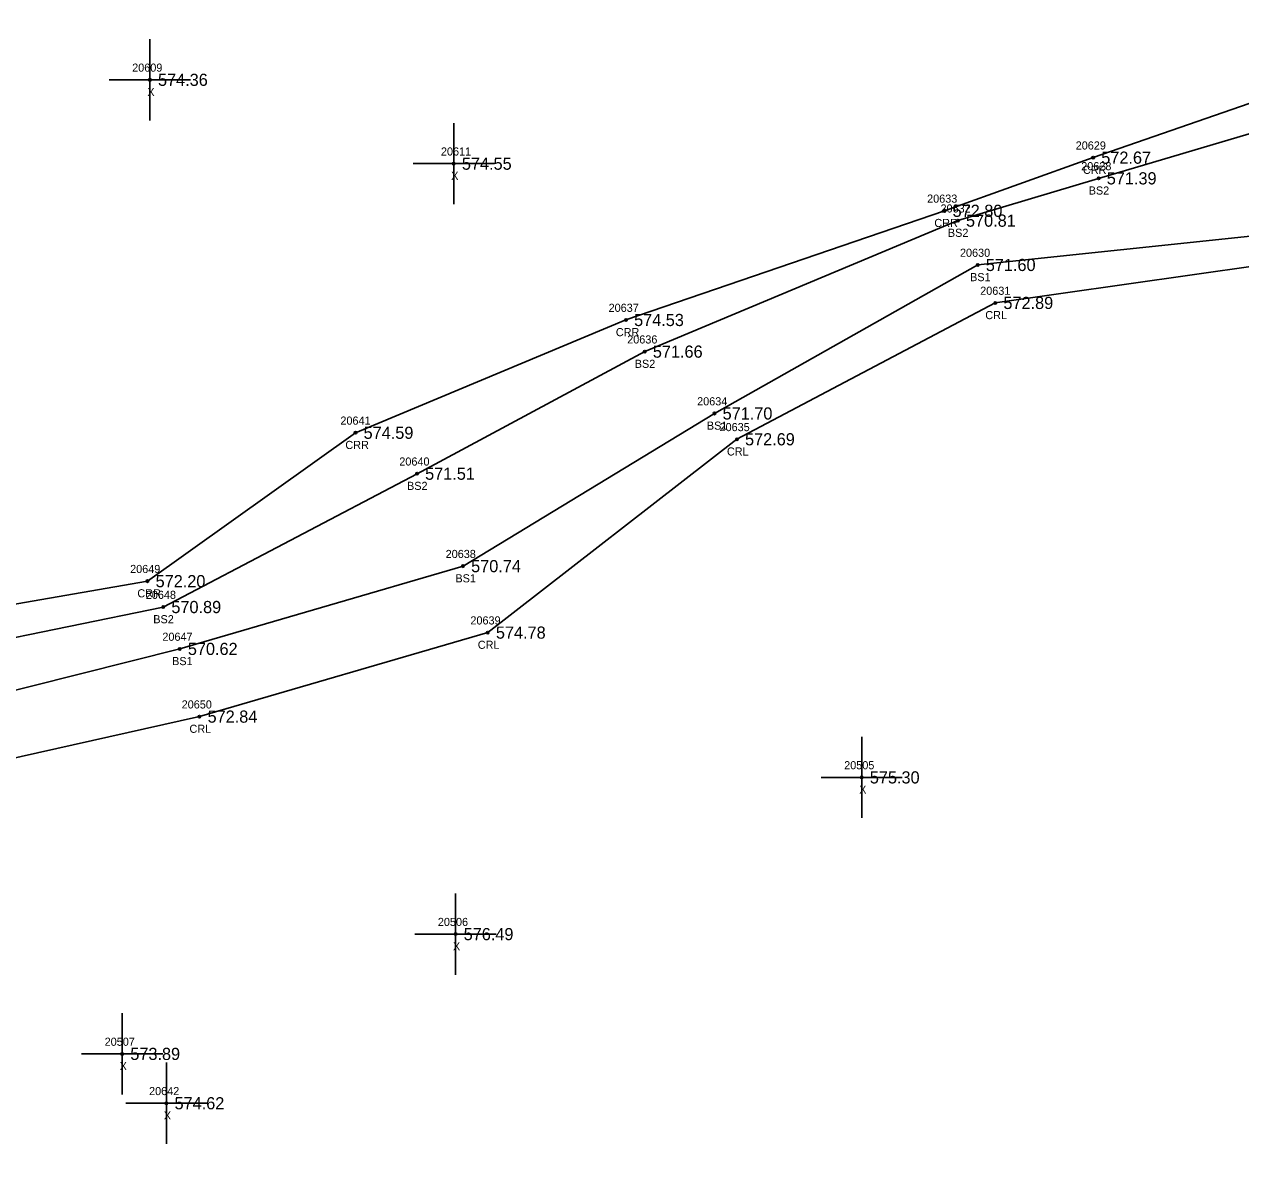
# Model space of a CAD drawing. Extents: x 1664837 to 1666270, y 987403 to 988245.
# Drawn here: x 1665313 to 1665462.9, y 987586.1 to 987728.5 of the extents above; entities that cross this region are included whole.
import ezdxf

# ---------------------------------------------------------------- set-up
doc = ezdxf.new("R2010")
doc.units = 0
for name, color, linetype in [('RD_DTM_BkLn2', 7, 'Continuous'), ('RD_DTM_BkLn_txCode', 7, 'Continuous'), ('RD_EX_H2O', 7, 'Continuous'), ('RD_EX_H2O_txCode', 7, 'Continuous'), ('RD_EX_Misc', 7, 'Continuous'), ('RD_EX_Misc_txCode', 7, 'Continuous'), ('RD_EX_TX_H2O_ELEV', 7, 'Continuous'), ('RD_EX_TX_Misc_ELEV', 7, 'Continuous'), ('RD_SMD_Locator', 7, 'Continuous')]:
    doc.layers.add(name, color=color, linetype=linetype)

msp = doc.modelspace()

# ---------------------------------------------------------------- linework, layer by layer
at = {"layer": 'RD_DTM_BkLn2'}
for points in [[(1665511.23, 987778.14), (1665500.12, 987754.08), (1665496.26, 987735.63), (1665475.45, 987718.43), (1665445.39, 987709.52), (1665428.04, 987704.31), (1665389.45, 987688.17), (1665361.39, 987673.13), (1665330.12, 987656.7), (1665283.57, 987647.17), (1665235.53, 987667.53), (1665208.93, 987663.65), (1665168.4, 987630.38), (1665122.54, 987622.98), (1665093.74, 987624.1), (1665049.09, 987603.27)], [(1665468.58, 987700.71), (1665465.66, 987702.55), (1665430.48, 987698.85), (1665398.05, 987680.55), (1665367.06, 987661.74), (1665332.15, 987651.54), (1665283, 987639.17), (1665233.73, 987658.08), (1665210.97, 987648.76), (1665173.41, 987617.25), (1665124.74, 987609.31), (1665095.75, 987609.41), (1665057.17, 987591.87)]]:
    msp.add_lwpolyline(points, dxfattribs=at)
at = {"layer": 'RD_EX_H2O'}
for points in [[(1665498.75, 987759.37), (1665497.35, 987756.86), (1665493.15, 987755.47), (1665489.09, 987748.98), (1665492.34, 987734.97), (1665472.46, 987721.68), (1665444.71, 987712.07), (1665426.39, 987705.52), (1665387.14, 987692.07), (1665353.81, 987678.17), (1665328.18, 987659.89), (1665283.87, 987652.21), (1665224.39, 987676.29), (1665206.47, 987666.98), (1665167.33, 987633.9), (1665123.23, 987629.54), (1665093.05, 987625.54), (1665046.91, 987607.08)], [(1665465.98, 987698.59), (1665465.01, 987698.79), (1665432.65, 987694.17), (1665400.81, 987677.37), (1665370.11, 987653.55), (1665334.58, 987643.2), (1665283.82, 987631.84), (1665232.68, 987646.81), (1665216.29, 987640.35), (1665180.84, 987613.76), (1665127.14, 987605.7), (1665095.77, 987606.5), (1665062.74, 987586.14)]]:
    msp.add_lwpolyline(points, dxfattribs=at)
at = {"layer": 'RD_EX_Misc'}
for p, q in [((1665328.47, 987716.66), (1665328.47, 987726.66)), ((1665323.47, 987721.66), (1665333.47, 987721.66)), ((1665365.92, 987706.33), (1665365.92, 987716.33)), ((1665360.92, 987711.33), (1665370.92, 987711.33)), ((1665416.19, 987630.71), (1665416.19, 987640.71)), ((1665411.19, 987635.71), (1665421.19, 987635.71)), ((1665366.14, 987611.4), (1665366.14, 987621.4)), ((1665361.14, 987616.4), (1665371.14, 987616.4)), ((1665325.06, 987596.64), (1665325.06, 987606.64)), ((1665320.06, 987601.64), (1665330.06, 987601.64)), ((1665330.51, 987590.56), (1665330.51, 987600.56)), ((1665325.51, 987595.56), (1665335.51, 987595.56))]:
    msp.add_line(p, q, dxfattribs=at)
at = {"layer": 'RD_SMD_Locator'}
for centre in [(1665328.47, 987721.66), (1665444.71, 987712.07), (1665365.92, 987711.33), (1665445.39, 987709.52), (1665426.39, 987705.52), (1665428.04, 987704.31), (1665430.48, 987698.85), (1665432.65, 987694.17), (1665387.14, 987692.07), (1665389.45, 987688.17), (1665398.05, 987680.55), (1665353.81, 987678.17), (1665400.81, 987677.37), (1665361.39, 987673.13), (1665367.06, 987661.74), (1665328.18, 987659.89), (1665330.12, 987656.7), (1665370.11, 987653.55), (1665332.15, 987651.54), (1665334.58, 987643.2), (1665416.19, 987635.71), (1665366.14, 987616.4), (1665325.06, 987601.64), (1665330.51, 987595.56)]:
    msp.add_circle(centre, 0.15, dxfattribs=at)

# ---------------------------------------------------------------- texts
at = {"layer": 'RD_DTM_BkLn_txCode'}
for s, p in [('20628', (1665443.24, 987710.52)), ('BS2', (1665444.16, 987707.52)), ('20632', (1665425.9, 987705.31)), ('BS2', (1665426.81, 987702.31)), ('20630', (1665428.3, 987699.85)), ('BS1', (1665429.54, 987696.85)), ('20636', (1665387.29, 987689.17)), ('BS2', (1665388.22, 987686.17)), ('20634', (1665395.91, 987681.55)), ('BS1', (1665397.11, 987678.55)), ('20640', (1665359.21, 987674.13)), ('BS2', (1665360.16, 987671.13)), ('20638', (1665364.92, 987662.74)), ('BS1', (1665366.12, 987659.74)), ('20648', (1665327.97, 987657.7)), ('BS2', (1665328.89, 987654.7)), ('20647', (1665330.01, 987652.54)), ('BS1', (1665331.21, 987649.54))]:
    msp.add_text(s, height=1, dxfattribs=at).set_placement(p)
at = {"layer": 'RD_EX_H2O_txCode'}
for s, p in [('20629', (1665442.56, 987713.07)), ('CRR', (1665443.45, 987710.07)), ('20633', (1665424.25, 987706.52)), ('CRR', (1665425.14, 987703.52)), ('20631', (1665430.79, 987695.17)), ('20637', (1665385, 987693.07)), ('CRL', (1665431.42, 987692.17)), ('CRR', (1665385.89, 987690.07)), ('20641', (1665351.95, 987679.17)), ('20635', (1665398.67, 987678.37)), ('CRR', (1665352.56, 987676.17)), ('CRL', (1665399.58, 987675.37)), ('20649', (1665326.04, 987660.89)), ('CRR', (1665326.93, 987657.89)), ('20639', (1665367.97, 987654.55)), ('CRL', (1665368.88, 987651.55)), ('20650', (1665332.39, 987644.2)), ('CRL', (1665333.35, 987641.2))]:
    msp.add_text(s, height=1, dxfattribs=at).set_placement(p)
at = {"layer": 'RD_EX_Misc_txCode'}
for s, p in [('20609', (1665326.29, 987722.66)), ('X', (1665328.16, 987719.66)), ('20611', (1665364.34, 987712.33)), ('X', (1665365.6, 987709.33)), ('20505', (1665414.03, 987636.71)), ('X', (1665415.88, 987633.71)), ('20506', (1665363.96, 987617.4)), ('X', (1665365.82, 987614.4)), ('20507', (1665322.9, 987602.64)), ('X', (1665324.75, 987599.64)), ('20642', (1665328.37, 987596.56)), ('X', (1665330.19, 987593.56))]:
    msp.add_text(s, height=1, dxfattribs=at).set_placement(p)
at = {"layer": 'RD_EX_TX_H2O_ELEV'}
for s, p in [('572.67', (1665445.71, 987711.32)), ('572.80', (1665427.39, 987704.77)), ('572.89', (1665433.65, 987693.42)), ('574.53', (1665388.14, 987691.32)), ('574.59', (1665354.81, 987677.42)), ('572.69', (1665401.81, 987676.62)), ('572.20', (1665329.18, 987659.14)), ('574.78', (1665371.11, 987652.8)), ('572.84', (1665335.58, 987642.45))]:
    msp.add_text(s, height=1.5, dxfattribs=at).set_placement(p)
at = {"layer": 'RD_EX_TX_Misc_ELEV'}
for s, p in [('574.36', (1665329.47, 987720.91)), ('574.55', (1665366.92, 987710.58)), ('571.39', (1665446.39, 987708.77)), ('570.81', (1665429.04, 987703.56)), ('571.60', (1665431.48, 987698.1)), ('571.66', (1665390.45, 987687.42)), ('571.70', (1665399.05, 987679.8)), ('571.51', (1665362.39, 987672.38)), ('570.74', (1665368.06, 987660.99)), ('570.89', (1665331.12, 987655.95)), ('570.62', (1665333.15, 987650.79)), ('575.30', (1665417.19, 987634.96)), ('576.49', (1665367.14, 987615.65)), ('573.89', (1665326.06, 987600.89)), ('574.62', (1665331.51, 987594.81))]:
    msp.add_text(s, height=1.5, dxfattribs=at).set_placement(p)

doc.saveas('drawing.dxf')
